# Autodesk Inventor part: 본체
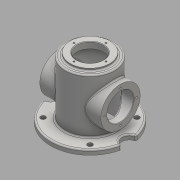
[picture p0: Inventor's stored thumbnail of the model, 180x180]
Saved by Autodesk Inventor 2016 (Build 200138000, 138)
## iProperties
Created: 2018-04
Part Number: 본체
Material: 일반
Document SubType Name: Modeling
Designer: 605-17
Density: 1 g/cm^3
Appearance: 기본값
Author: 605-17
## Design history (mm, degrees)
sketch "스케치1"
  geometry: C1 r 50 at (0, 0); 1 further point
  constraints: 1 centre point, 1 coincident
  dimensions: "d0" = 100 diameter of C1
extrude "돌출1" new body sketch "스케치1" distance "d1" = 128; taper "d2" = 0 deg
sketch "스케치2"
  geometry: C1 r 40 at (0, 0); 1 further point
  constraints: 1 centre point, 1 coincident
  dimensions: "d3" = 80 diameter of C1
extrude "돌출2" join sketch "스케치2" distance "d4" = 5; taper "d5" = 0 deg
node "작업 평면1"
sketch "스케치3"
  geometry: C1 r 80 at (0, 0); 1 further point
  constraints: 1 centre point, 1 coincident
  dimensions: "d7" = 160 diameter of C1
extrude "돌출3" join sketch "스케치3" distance "d8" = 10; taper "d9" = 0 deg
sketch "스케치6"
  geometry: L1 (-80, 8)-(80, 8) reference; C1 r 40 at (0, 68); 1 further point
  constraints: 1 centre point
  dimensions: "d16" = 80 diameter of C1; "d17" = 60 distance from line of C1.centre L1
extrude "돌출6" join sketch "스케치6" stored distance "d18" = 124; taper "d19" = 0 deg
sketch "스케치4"
  geometry: C1 r 27 at (0, 0); 1 further point
  constraints: 1 centre point, 1 coincident
  dimensions: "d10" = 54 diameter of C1
extrude "돌출4" cut sketch "스케치4" distance "d11" = 13; taper "d12" = 0 deg
sketch "스케치5"
  geometry: C1 r 45 at (0, 0); 1 further point
  constraints: 1 centre point, 1 coincident
  dimensions: "d13" = 90 diameter of C1
extrude "돌출5" cut sketch "스케치5" distance "d14" = 120; taper "d15" = 0 deg
sketch "스케치7"
  geometry: C1 r 27 at (0, 0); 1 further point
  constraints: 1 centre point
  dimensions: "d20" = 54 diameter of C1
extrude "돌출7" cut sketch "스케치7" stored distance "d21" = 124; taper "d22" = 0 deg
sketch "스케치8"
  geometry: L1 (0, 0)-(32.5, 0); 2 further points
  constraints: 2 end point, 1 coincident, 1 horizontal
  dimensions: "d23" = 32.5 distance of L1.start L1.end
hole "구멍1" sketch "스케치8" at (0, 0), (32.5, 0) diameter "d24" = 3.242; stored, may be unused: countersink angle "d28" = 90 deg, drill point angle "d30" = 118 deg; dims "d25" = 8, "d26" = 4, "d27" = 2, "d29" = 10
sketch "스케치9"
  geometry: L1 (0, 0)-(0, -32.5); C1 r 45 at (0, 0) reference; 2 further points
  constraints: 2 end point, 1 coincident, 1 vertical
  dimensions: "d34" = 32.5 distance of L1.start L1.end
hole "구멍2" sketch "스케치9" at (0, -32.5) diameter "d35" = 3.242; stored, may be unused: countersink angle "d39" = 90 deg, drill point angle "d41" = 118 deg; dims "d36" = 8, "d37" = 4, "d38" = 2, "d40" = 10
sketch "스케치10"
  geometry: C1 r 15 at (-80, 0); 2 further points
  constraints: 1 centre point, 1 horizontal alignment, 1 other
  dimensions: "d45" = 30 diameter of C1
extrude "돌출8" cut sketch "스케치10" distance "d46" = 10; taper "d47" = 0 deg
sketch "스케치11"
  geometry: L1 (0, 0)-(67.5, 0); C1 r 5 at (47.73, -47.73)
  constraints: 2 end point, 1 centre point, 1 horizontal
  dimensions: "d50" = 10 diameter of C1
extrude "돌출9" cut sketch "스케치11" distance "d51" = 10; taper "d52" = 0 deg
chamfer "모따기1" distance "d56" = 1; stored, may be unused: second distance "d57" = 2, angle "d58" = 45 deg
fillet "모깎기1" dims "d59" = 3
fillet "모깎기2" dims "d60" = 3
node "작업 평면2"
sketch "스케치12"
  geometry: L1 (-14.195, 38.156)-(-14.195, 117.844); L2 (-14.195, 117.844)-(13.853, 117.844); L3 (13.853, 117.844)-(13.853, 38.156); L4 (13.853, 38.156)-(-14.195, 38.156); L5 (-0.171, 38.156)-(-0.171, 117.844); L6 (-14.195, 78)-(13.853, 78); L7 (-77.955, 8)-(77.955, 8) reference; 2 further points
  constraints: 5 midpoint, 4 end point, 2 other
  dimensions: "d62" = 70 distance from line of L7 point (-0.171, 78)
feature "엠보싱1" sketch "스케치12" dims "d1" = 128, "d2" = 0, "d63" = 0.5, "d64" = 0
node "솔리드1"
pattern_circular "원형 패턴1" dims angle "d32" = 360 deg
mirror "대칭1"
pattern_circular "원형 패턴2" dims angle "d43" = 360 deg
mirror "대칭2"
pattern_circular "원형 패턴3" dims angle "d54" = 360 deg
other parameters: "d6" = 8, "d61" = 113.25
